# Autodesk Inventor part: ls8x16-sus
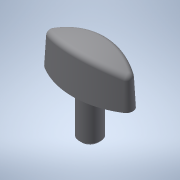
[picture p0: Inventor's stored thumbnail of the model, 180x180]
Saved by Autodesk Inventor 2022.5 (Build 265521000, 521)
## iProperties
Created: 2016-12
Part Number: ls8x16-sus
Material: 一般
Document SubType Name: Modeling
Designer: imaocorp
Density: 1 g/cm^3
Appearance: 既定
Author: imaocorp
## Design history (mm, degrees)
node "ls8x16-sus.x_t1"
node "ls8x16-sus"
node "Base1"
